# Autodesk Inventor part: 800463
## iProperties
Created: 2007-10
Part Number: 800463
Document SubType Name: Modeling
Designer: JC
Density: 7.84 g/cm^3
Mass: 9.36188 g
Surface Area: 7.72974 cm^2
Volume: 1.19412 cm^3
Material: Steel, High Strength Low Alloy
Description: PIVOT PIN
Component Category: Fasteners
Author: JC
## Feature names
1. Extrusion1
2. Extrusion2
3. Fillet1
4. Chamfer2
